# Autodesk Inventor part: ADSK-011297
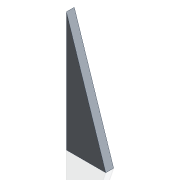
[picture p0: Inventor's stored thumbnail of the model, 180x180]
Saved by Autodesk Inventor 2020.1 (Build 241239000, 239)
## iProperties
Created: 1999-11
Part Number: ADSK-011297
Material: Pearson Aluminium
Document SubType Name: Modeling
Designer: sspink
Density: 2.71 g/cm^3
Appearance: Pearson-Aluminum
Mass: 102.98 g
Surface Area: 112.201 cm^2
Volume: 38 cm^3
Control State: 0
Checked Out: False
Last Check In By: sspink
Last Check In Date: 1999-12-22
Master: False
Shininess: 35.0
Length Units: 11269
Angle Units: 11279
Time Units: 11290
Mass Units: 11283
Length Display Precision: 3
Angle Display Precision: 2
Compacted: True
Cutlength: 6
Material Desc: FLAT,ALUM,0.375 X 2.00
Material_number: A084024
Dimensions: 50x152x10 mm
Mass: 0,103 kg
DocNumber: ADSK-011297.ipt
Folder: 01 - Themengebiete\Simplification\01 - Packaging machine\
VDS_Category: 3D Komponenten
Density: 2.71
Volumn: 36.87089399999999
Area: 112.07531291425667
PropertySet Name: Model Information
Author: sspink
Revision Number: -
Title: support
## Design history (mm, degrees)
node "Solide1"
  node "Extrusion1" dims "d2" = 10, "d3" = 0
sketch "Sketch1"
  geometry: L1 (6.35, -0.4)-(56.35, -152.4); L2 (56.35, -152.4)-(6.35, -152.4); L3 (6.35, -152.4)-(6.35, -0.4)
  constraints: 6 end point, 1 horizontal, 1 perpendicular
  dimensions: "d0" = 50 distance of L2.end L1.end; "d1" = 152 distance of L2.end L1.start
node "Corps solides"
node "Corps surfaciques"
